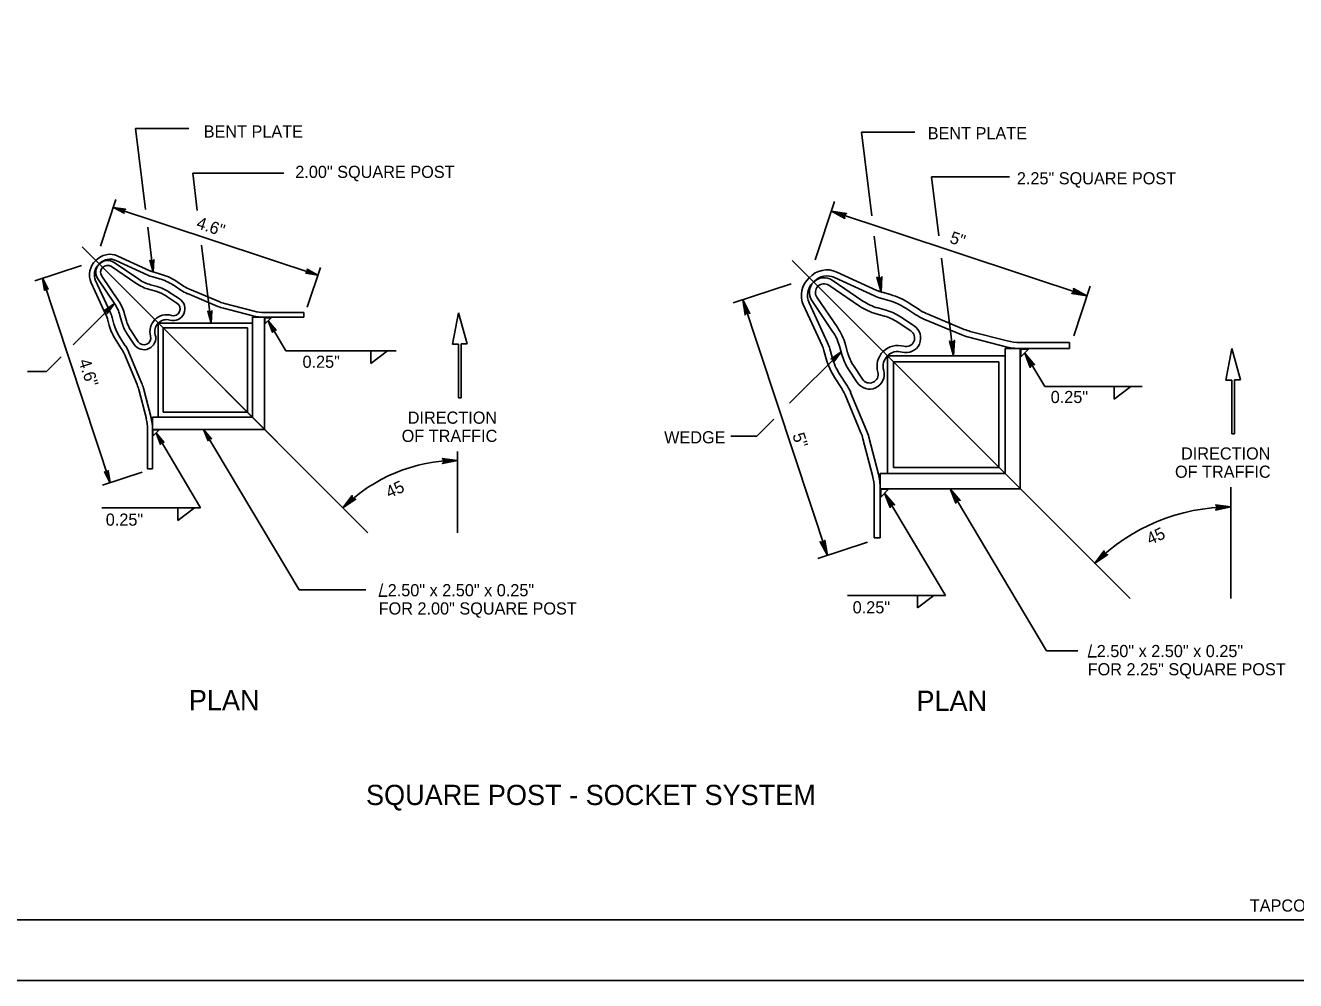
# Model space of a CAD drawing. Extents: x 644358 to 648627, y 294594 to 295782.
# Drawn here: x 646287.7 to 646601.4, y 294593.6 to 294829.5 of the extents above; entities that cross this region are included whole.
import ezdxf

# ---------------------------------------------------------------- set-up
doc = ezdxf.new("R2010")
doc.units = 0
for name, color, linetype in [('1', 7, 'Continuous'), ('2', 7, 'Continuous'), ('3', 7, 'Continuous'), ('4', 7, 'Continuous'), ('PLT-BNDY', 7, 'Continuous')]:
    doc.layers.add(name, color=color, linetype=linetype)

# ---------------------------------------------------------------- blocks, each defined once
blk = doc.blocks.new('RARROW')
at = {"layer": '3'}
blk.add_lwpolyline([(-2.2695, 0.285), (-2.184875, 0.12075), (0, 0), (-2.2695, 0.285), (-2.38575, 0.384625), (0, 0), (-2.183125, -0.108), (-2.262875, -0.2705), (0, 0), (-2.38575, -0.379125), (-2.262875, -0.2705)], dxfattribs=at)

msp = doc.modelspace()

# ---------------------------------------------------------------- linework, layer by layer
at = {"layer": '1'}
for p, q in [((646349.95, 294726.54), (646301.7, 294774.79)), ((646372.29, 294704.2), (646301.7, 294774.79)), ((646305.76, 294770.39), (646305.93, 294770.56)), ((646306.1, 294770.73), (646305.93, 294770.56)), ((646560.51, 294687.94), (646477.06, 294771.4)), ((646537.36, 294711.09), (646477.06, 294771.4)), ((646482.12, 294765.9), (646482.34, 294766.12)), ((646482.55, 294766.33), (646482.34, 294766.12)), ((646394.41, 294724.29), (646394.41, 294704.2)), ((646585.37, 294715.44), (646585.37, 294687.94)), ((646866.31, 294608.63), (646080.31, 294608.63)), ((646080.31, 294608.63), (646666.31, 294608.63))]:
    msp.add_line(p, q, dxfattribs=at)
at = {"layer": '2'}
for p, q in [((646317.37, 294784.03), (646314.91, 294804.02)), ((646314.91, 294804.02), (646328.06, 294804.02)), ((646496.7, 294782.46), (646494.15, 294803.13)), ((646494.15, 294803.13), (646507.31, 294803.13)), ((646330.15, 294783.77), (646329.02, 294792.97)), ((646329.02, 294792.97), (646351.48, 294792.97)), ((646513.25, 294777.55), (646511.45, 294792.08)), ((646511.45, 294792.08), (646530.73, 294792.08)), ((646306.27, 294774.97), (646310.07, 294786.45)), ((646482.76, 294771.63), (646487.51, 294785.98)), ((646309.44, 294784.55), (646359.94, 294767.84)), ((646486.72, 294783.61), (646549.85, 294762.71)), ((646319.28, 294768.57), (646317.91, 294779.64)), ((646499.03, 294763.63), (646497.32, 294777.47)), ((646333.58, 294755.98), (646331.21, 294775.24)), ((646301.52, 294770.22), (646290.04, 294766.43)), ((646516.91, 294747.89), (646513.93, 294771.97)), ((646357.32, 294759.94), (646360.56, 294769.74)), ((646291.94, 294767.05), (646308.65, 294716.55)), ((646476.82, 294765.7), (646462.48, 294760.95)), ((646546.58, 294752.84), (646550.63, 294765.09)), ((646309.69, 294760.81), (646299.5, 294750.62)), ((646464.85, 294761.73), (646485.74, 294698.61)), ((646394.68, 294758.54), (646393.2, 294750.74)), ((646396.8, 294750.82), (646394.68, 294758.54)), ((646348.4, 294757.31), (646346.86, 294755.76)), ((646346.86, 294755.76), (646346.86, 294757.31)), ((646346.86, 294757.31), (646348.4, 294757.31)), ((646347.63, 294756.53), (646352.04, 294749.12)), ((646352.04, 294749.12), (646379.29, 294749.12)), ((646373.03, 294746.02), (646373.03, 294749.12)), ((646377.08, 294749.12), (646373.03, 294746.02)), ((646393.2, 294750.74), (646394.65, 294750.74)), ((646394.65, 294750.74), (646394.65, 294737.49)), ((646395.35, 294737.49), (646395.35, 294750.82)), ((646395.35, 294750.82), (646396.8, 294750.82)), ((646489.12, 294748.9), (646476.38, 294736.17)), ((646535.43, 294749.55), (646533.5, 294747.62)), ((646533.5, 294747.62), (646533.5, 294749.55)), ((646533.5, 294749.55), (646535.43, 294749.55)), ((646534.46, 294748.58), (646539.4, 294740.28)), ((646585.64, 294749.7), (646584.16, 294741.89)), ((646587.75, 294741.97), (646585.64, 294749.7)), ((646296.55, 294747.67), (646292.89, 294744.01)), ((646288.25, 294744.01), (646292.89, 294744.01)), ((646586.31, 294728.65), (646586.31, 294741.97)), ((646586.31, 294741.97), (646587.75, 294741.97)), ((646539.4, 294740.28), (646563.46, 294740.28)), ((646556.6, 294737.16), (646556.6, 294740.28)), ((646560.66, 294740.28), (646556.6, 294737.16)), ((646584.16, 294741.89), (646585.6, 294741.89)), ((646585.6, 294741.89), (646585.6, 294728.65)), ((646394.65, 294737.49), (646395.35, 294737.49)), ((646320.73, 294729.64), (646319.18, 294728.09)), ((646319.18, 294728.09), (646319.18, 294729.64)), ((646319.18, 294729.64), (646320.73, 294729.64)), ((646331.72, 294729.74), (646355.3, 294690.09)), ((646472.5, 294732.28), (646468.29, 294728.07)), ((646319.96, 294728.86), (646330.97, 294710.35)), ((646461.87, 294728.07), (646468.29, 294728.07)), ((646585.6, 294728.65), (646586.31, 294728.65)), ((646316.55, 294719.17), (646306.75, 294715.93)), ((646500.84, 294714.96), (646498.91, 294713.03)), ((646498.91, 294713.03), (646498.91, 294714.96)), ((646498.91, 294714.96), (646500.84, 294714.96)), ((646499.87, 294713.99), (646514.89, 294688.75)), ((646516.08, 294715.09), (646539.88, 294675.08)), ((646306.56, 294710.35), (646330.97, 294710.35)), ((646325.35, 294707.19), (646325.35, 294710.35)), ((646329.48, 294710.35), (646325.35, 294707.19)), ((646495.62, 294701.88), (646483.37, 294697.82)), ((646355.3, 294690.09), (646371.78, 294690.09)), ((646490.75, 294688.75), (646514.89, 294688.75)), ((646507.99, 294685.69), (646507.99, 294688.75)), ((646511.99, 294688.75), (646507.99, 294685.69)), ((646375.01, 294688.51), (646377.07, 294688.51)), ((646539.88, 294675.08), (646547.57, 294675.08)), ((646550.16, 294673.57), (646552.22, 294673.57))]:
    msp.add_line(p, q, dxfattribs=at)
for centre, radius, start, end in [((646321.29, 294775.07), 6.8, 245.3297, 254.5668), ((646501.54, 294771.76), 8.5, 245.3297, 254.5668), ((646394.41, 294682.08), 40, 90, 135), ((646585.37, 294663.09), 47.5, 90, 135)]:
    msp.add_arc(centre, radius, start, end, dxfattribs=at)
at = {"layer": '3'}
for p, q in [((646315.68, 294766.8), (646309.61, 294770.91)), ((646310.04, 294771.44), (646317.95, 294767.8)), ((646310.54, 294772.53), (646318.45, 294768.89)), ((646310.69, 294761.49), (646306.57, 294767.56)), ((646315, 294765.8), (646308.93, 294769.92)), ((646320.78, 294766.91), (646319.16, 294767.36)), ((646321.1, 294768.07), (646319.48, 294768.52)), ((646487.47, 294767.21), (646497.36, 294762.67)), ((646488.1, 294768.58), (646497.99, 294764.03)), ((646303.96, 294765.95), (646307.6, 294758.04)), ((646305.05, 294766.45), (646308.69, 294758.54)), ((646309.69, 294760.81), (646305.58, 294766.88)), ((646319.93, 294763.83), (646318.31, 294764.28)), ((646320.25, 294764.99), (646318.63, 294765.43)), ((646324.18, 294765.38), (646326.11, 294764.11)), ((646324.84, 294766.38), (646326.76, 294765.11)), ((646493.68, 294760.17), (646486.09, 294765.31)), ((646494.52, 294761.41), (646486.94, 294766.56)), ((646322.42, 294762.7), (646325.12, 294760.92)), ((646323.08, 294763.7), (646325.78, 294761.93)), ((646481.24, 294760.98), (646485.79, 294751.09)), ((646487.04, 294753.93), (646481.9, 294761.52)), ((646488.29, 294754.78), (646483.14, 294762.36)), ((646500.9, 294761.56), (646498.88, 294762.12)), ((646501.3, 294763.01), (646499.27, 294763.57)), ((646505.97, 294760.89), (646508.38, 294759.31)), ((646311.5, 294756.24), (646311.06, 294757.86)), ((646312.66, 294756.56), (646312.21, 294758.18)), ((646346.68, 294758.61), (646356.48, 294758.61)), ((646356.48, 294757.41), (646356.48, 294758.61)), ((646479.88, 294760.36), (646484.42, 294750.47)), ((646499.84, 294757.7), (646497.81, 294758.26)), ((646500.23, 294759.15), (646498.21, 294759.71)), ((646505.15, 294759.64), (646507.56, 294758.05)), ((646308.42, 294755.39), (646307.97, 294757.01)), ((646309.58, 294755.71), (646309.13, 294757.33)), ((646320.51, 294755.98), (646320.51, 294732.74)), ((646320.51, 294755.98), (646343.76, 294755.98)), ((646321.71, 294754.78), (646321.71, 294733.94)), ((646321.71, 294754.78), (646342.56, 294754.78)), ((646342.56, 294754.78), (646342.56, 294733.94)), ((646343.76, 294757.41), (646343.76, 294732.74)), ((646343.76, 294757.41), (646346.68, 294757.41)), ((646346.68, 294757.41), (646356.48, 294757.41)), ((646346.76, 294757.41), (646346.76, 294729.74)), ((646502.95, 294756.29), (646506.33, 294754.07)), ((646503.77, 294757.55), (646507.16, 294755.32)), ((646310.11, 294751.66), (646311.38, 294749.73)), ((646311.12, 294752.31), (646312.38, 294750.39)), ((646312.79, 294753.41), (646314.56, 294750.71)), ((646313.79, 294754.07), (646315.57, 294751.37)), ((646485.45, 294747.16), (646484.89, 294749.18)), ((646486.9, 294747.56), (646486.34, 294749.58)), ((646489.31, 294748.22), (646488.75, 294750.25)), ((646490.75, 294748.62), (646490.19, 294750.65)), ((646529.62, 294749.68), (646529.62, 294718.84)), ((646529.62, 294749.68), (646533.28, 294749.68)), ((646533.28, 294751.18), (646545.53, 294751.18)), ((646533.28, 294749.68), (646545.53, 294749.68)), ((646533.37, 294749.68), (646533.37, 294715.09)), ((646545.53, 294749.68), (646545.53, 294751.18)), ((646492.16, 294745.51), (646494.39, 294742.12)), ((646500.57, 294747.89), (646500.57, 294718.84)), ((646500.57, 294747.89), (646529.62, 294747.89)), ((646502.07, 294746.39), (646502.07, 294720.34)), ((646502.07, 294746.39), (646528.12, 294746.39)), ((646528.12, 294746.39), (646528.12, 294720.34)), ((646487.57, 294742.49), (646489.15, 294740.07)), ((646488.82, 294743.31), (646490.41, 294740.9)), ((646490.91, 294744.68), (646493.13, 294741.3)), ((646319.08, 294732.74), (646343.76, 294732.74)), ((646319.08, 294732.74), (646319.08, 294729.81)), ((646321.71, 294733.94), (646342.56, 294733.94)), ((646317.88, 294729.81), (646317.88, 294720.01)), ((646319.08, 294729.81), (646319.08, 294720.01)), ((646319.08, 294729.74), (646346.76, 294729.74)), ((646502.07, 294720.34), (646528.12, 294720.34)), ((646319.08, 294720.01), (646317.88, 294720.01)), ((646498.78, 294718.84), (646529.62, 294718.84)), ((646498.78, 294718.84), (646498.78, 294715.18)), ((646497.28, 294715.18), (646497.28, 294702.93)), ((646498.78, 294715.18), (646498.78, 294702.93)), ((646498.78, 294715.09), (646533.37, 294715.09)), ((646498.78, 294702.93), (646497.28, 294702.93))]:
    msp.add_line(p, q, dxfattribs=at)
for points in [[(646328.2, 294764.35), (646335.69, 294761.21)], [(646327.74, 294763.24), (646335.23, 294760.11)], [(646336.89, 294760.81), (646344.18, 294758.93)], [(646336.59, 294759.65), (646343.88, 294757.76)], [(646510.18, 294758.35), (646519.54, 294754.43)], [(646509.6, 294756.97), (646518.96, 294753.05)], [(646520.66, 294752.48), (646529.77, 294750.12)], [(646521.03, 294753.93), (646530.15, 294751.57)], [(646312.15, 294748.29), (646315.28, 294740.8)], [(646313.25, 294748.75), (646316.39, 294741.26)], [(646315.68, 294739.61), (646317.57, 294732.31)], [(646316.84, 294739.91), (646318.73, 294732.61)], [(646491.49, 294738.86), (646495.41, 294729.49)], [(646490.11, 294738.28), (646494.02, 294728.91)], [(646494.53, 294727.42), (646496.88, 294718.31)], [(646495.98, 294727.8), (646498.34, 294718.69)]]:
    msp.add_lwpolyline(points, dxfattribs=at)
for centre, radius, start, end in [((646308.23, 294767.91), 4.7, 132.0461, 204.6703), ((646308.23, 294767.91), 3.5, 135, 204.6703), ((646307.98, 294768.51), 2.9, 135, 214.1353), ((646308.58, 294768.26), 4.7, 65.3297, 137.9539), ((646307.98, 294768.51), 2.9, 55.8647, 135), ((646308.58, 294768.26), 3.5, 65.3297, 135), ((646307.98, 294768.51), 1.7, 55.8647, 135), ((646307.98, 294768.51), 1.7, 135, 214.1353), ((646321.29, 294775.07), 8, 245.3297, 254.5668), ((646317.59, 294755.35), 13.2, 56.6854, 74.5668), ((646485.22, 294762.81), 5.88, 132.0461, 204.6703), ((646485.65, 294763.24), 5.88, 65.3297, 137.9539), ((646484.9, 294763.56), 3.62, 55.8647, 135), ((646485.65, 294763.24), 4.38, 65.3297, 135), ((646321.29, 294775.07), 11.2, 235.8647, 254.5668), ((646321.29, 294775.07), 10, 235.8647, 254.5668), ((646317.59, 294755.35), 10, 56.6854, 74.5668), ((646317.59, 294755.35), 12, 56.6854, 74.5668), ((646331.6, 294772.46), 10, 236.6854, 247.3023), ((646331.6, 294772.46), 8.8, 236.6854, 247.3023), ((646485.22, 294762.81), 4.38, 135, 204.6703), ((646484.9, 294763.56), 3.62, 135, 214.1353), ((646484.9, 294763.56), 2.12, 135, 214.1353), ((646484.9, 294763.56), 2.12, 55.8647, 135), ((646301.42, 294755.2), 10, 15.4332, 34.1353), ((646301.42, 294755.2), 11.2, 15.4332, 34.1353), ((646317.59, 294755.35), 8.8, 56.6854, 74.5668), ((646324.19, 294759.5), 2.9, 254.3625, 56.685), ((646324.19, 294759.5), 1.7, 254.3625, 56.685), ((646339.09, 294769.33), 8.8, 247.3023, 255.4975), ((646501.54, 294771.76), 12.5, 235.8647, 254.5668), ((646501.54, 294771.76), 10, 245.3297, 254.5668), ((646496.91, 294747.1), 15, 56.6854, 74.5668), ((646496.91, 294747.1), 16.5, 56.6854, 74.5668), ((646301.42, 294755.2), 6.8, 15.4332, 24.6703), ((646301.42, 294755.2), 8, 15.4332, 24.6703), ((646322.57, 294753.93), 4.1, 73.2172, 135.2227), ((646339.09, 294769.33), 10, 247.3023, 255.4975), ((646346.68, 294768.61), 11.2, 255.4975, 270), ((646346.68, 294768.61), 10, 255.4975, 270), ((646501.54, 294771.76), 14, 235.8647, 254.5668), ((646496.91, 294747.1), 11, 56.6854, 74.5668), ((646496.91, 294747.1), 12.5, 56.6854, 74.5668), ((646514.42, 294768.5), 12.5, 236.6854, 247.3023), ((646514.42, 294768.5), 11, 236.6854, 247.3023), ((646321.14, 294758.91), 13.2, 195.4332, 213.3146), ((646321.14, 294758.91), 12, 195.4332, 213.3146), ((646321.14, 294758.91), 10, 195.4332, 213.3146), ((646321.14, 294758.91), 8.8, 195.4332, 213.3146), ((646322.56, 294753.92), 4.1, 134.7773, 196.7828), ((646322.56, 294753.92), 2.9, 134.7773, 196.7828), ((646322.57, 294753.93), 2.9, 73.2172, 135.2227), ((646476.7, 294746.92), 14, 15.4332, 34.1353), ((646505.16, 294752.3), 3.62, 254.3625, 56.685), ((646316.99, 294752.3), 2.9, 213.315, 15.6375), ((646316.99, 294752.3), 1.7, 213.315, 15.6375), ((646476.7, 294746.92), 12.5, 15.4332, 34.1353), ((646505.16, 294752.3), 2.12, 254.3625, 56.685), ((646523.79, 294764.58), 12.5, 247.3023, 255.4975), ((646523.79, 294764.58), 11, 247.3023, 255.4975), ((646533.28, 294763.68), 12.5, 255.4975, 270), ((646304.03, 294744.89), 8.8, 22.6977, 33.3146), ((646304.03, 294744.89), 10, 22.6977, 33.3146), ((646476.7, 294746.92), 8.5, 15.4332, 24.6703), ((646476.7, 294746.92), 10, 15.4332, 24.6703), ((646501.36, 294751.55), 11, 195.4332, 213.3146), ((646503.12, 294745.32), 5.12, 134.7773, 196.7828), ((646503.14, 294745.34), 5.12, 73.2172, 135.2227), ((646503.14, 294745.34), 3.62, 73.2172, 135.2227), ((646533.28, 294763.68), 14, 255.4975, 270), ((646501.36, 294751.55), 16.5, 195.4332, 213.3146), ((646501.36, 294751.55), 15, 195.4332, 213.3146), ((646501.36, 294751.55), 12.5, 195.4332, 213.3146), ((646503.12, 294745.32), 3.62, 134.7773, 196.7828), ((646496.16, 294743.29), 3.62, 213.315, 15.6375), ((646496.16, 294743.29), 2.12, 213.315, 15.6375), ((646307.16, 294737.4), 8.8, 14.5025, 22.6977), ((646307.16, 294737.4), 10, 14.5025, 22.6977), ((646479.96, 294734.03), 11, 22.6977, 33.3146), ((646479.96, 294734.03), 12.5, 22.6977, 33.3146), ((646307.88, 294729.81), 11.2, 0, 14.5025), ((646307.88, 294729.81), 10, 0, 14.5025), ((646483.88, 294724.67), 12.5, 14.5025, 22.6977), ((646483.88, 294724.67), 11, 14.5025, 22.6977), ((646484.78, 294715.18), 12.5, 0, 14.5025), ((646484.78, 294715.18), 14, 0, 14.5025)]:
    msp.add_arc(centre, radius, start, end, dxfattribs=at)
at = {"layer": 'PLT-BNDY'}
msp.add_lwpolyline([(646040.31, 295187.63), (646881.31, 295187.63), (646881.31, 294593.63), (646040.31, 294593.63)], close=True, dxfattribs=at)

# ---------------------------------------------------------------- block references
at = {"layer": '2'}
for p, xscale, yscale, rotation in [((646309.44, 294784.55), 1.2574347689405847, 1.3092961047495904, 161.72234238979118), ((646486.72, 294783.61), 1.571793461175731, 1.6366201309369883, 161.72234238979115), ((646319.28, 294768.57), 1.2574347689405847, 1.3092961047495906, -83.5643877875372), ((646291.94, 294767.05), 1.2574347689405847, -1.3092961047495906, 108.27765761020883), ((646359.94, 294767.84), 1.2574347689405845, 1.3092961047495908, -18.430831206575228), ((646499.02, 294763.63), 1.571793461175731, 1.6366201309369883, -83.5643877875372), ((646549.85, 294762.71), 1.5717934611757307, 1.636620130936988, -18.430831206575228), ((646309.69, 294760.81), 1.257434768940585, -1.3092961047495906, 44.86487671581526), ((646464.85, 294761.73), 1.571793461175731, -1.6366201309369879, 108.27765761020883), ((646333.58, 294755.98), 1.2574347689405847, 1.3092961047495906, -83.5643877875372), ((646347.63, 294756.53), 1.257434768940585, 1.3092961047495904, 120.80429784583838), ((646516.9, 294747.89), 1.571793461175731, 1.6366201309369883, -83.5643877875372), ((646489.12, 294748.9), 1.257434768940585, -1.3092961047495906, 44.86487671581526), ((646534.46, 294748.58), 1.5717934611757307, 1.636620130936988, 120.80429784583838), ((646331.72, 294729.74), 1.257434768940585, 1.3092961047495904, 120.80429784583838), ((646319.96, 294728.86), 1.257434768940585, 1.3092961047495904, 120.80429784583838), ((646394.41, 294722.08), 1.571793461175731, 1.6366201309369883, 2.441123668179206), ((646308.65, 294716.55), 1.2574347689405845, -1.3092961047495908, -71.56916879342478), ((646499.87, 294713.99), 1.5717934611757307, 1.636620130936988, 120.80429784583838), ((646516.08, 294715.09), 1.5717934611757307, 1.636620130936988, 120.80429784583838), ((646366.12, 294710.37), 1.571793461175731, 1.6366201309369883, -136.74013509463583), ((646585.37, 294710.59), 1.571793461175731, 1.6366201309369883, 2.441123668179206), ((646485.74, 294698.61), 1.5717934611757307, -1.636620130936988, -71.56916879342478), ((646551.78, 294696.68), 1.571793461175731, 1.6366201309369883, -136.74013509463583)]:
    msp.add_blockref('RARROW', p, dxfattribs=dict(at, xscale=xscale, yscale=yscale, rotation=rotation))

# ---------------------------------------------------------------- texts
for s, height, p in [('BENT PLATE', 3, (646331.73, 294801.79)), ('BENT PLATE', 3, (646510.52, 294801.36)), ('2.00" SQUARE POST', 3, (646354.35, 294791.81)), ('2.25" SQUARE POST', 3, (646532.53, 294790.23)), ('0.25"', 3, (646356.13, 294744.93)), ('0.25"', 3, (646540.89, 294736.23)), ('DIRECTION', 3, (646382.12, 294731.13)), ('OF TRAFFIC', 3, (646380.62, 294726.63)), ('WEDGE', 3, (646445.43, 294726.28)), ('DIRECTION', 3, (646573.08, 294722.28)), ('OF TRAFFIC', 3, (646571.58, 294717.78)), ('0.25"', 3, (646307.55, 294705.95)), ('/ 2.50" x 2.50" x 0.25"', 3, (646374.94, 294688.52)), ('FOR 2.00" SQUARE POST', 3, (646374.94, 294684.02)), ('0.25"', 3, (646491.99, 294684.3)), ('/ 2.50" x 2.50" x 0.25"', 3, (646550.02, 294673.5)), ('FOR 2.25" SQUARE POST', 3, (646550.02, 294669)), ('PLAN', 5, (646328.06, 294660.38)), ('PLAN', 5, (646507.73, 294660.21)), ('SQUARE POST - SOCKET SYSTEM', 5, (646371.81, 294636.97)), ('TAPCO INDUSTRIES OR EQUAL', 3, (646590.05, 294610.66))]:
    msp.add_text(s, height=height, dxfattribs=at).set_placement(p)
for p in [(646377.55, 294712.65), (646565.42, 294701.12)]:
    msp.add_text('45', height=3, rotation=24.8378, dxfattribs=at).set_placement(p)
at = {"layer": '4'}
for s, rotation, p in [('4.6"', 341.6869, (646329.71, 294779.49)), ('5"', 341.6869, (646515.74, 294775.87)), ('4.6"', 288.3131, (646300.78, 294746.6)), ('5"', 288.3131, (646477.06, 294728.34))]:
    msp.add_text(s, height=3, rotation=rotation, dxfattribs=at).set_placement(p)

doc.saveas('drawing.dxf')
